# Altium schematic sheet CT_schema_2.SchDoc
size 287 x 169 mm
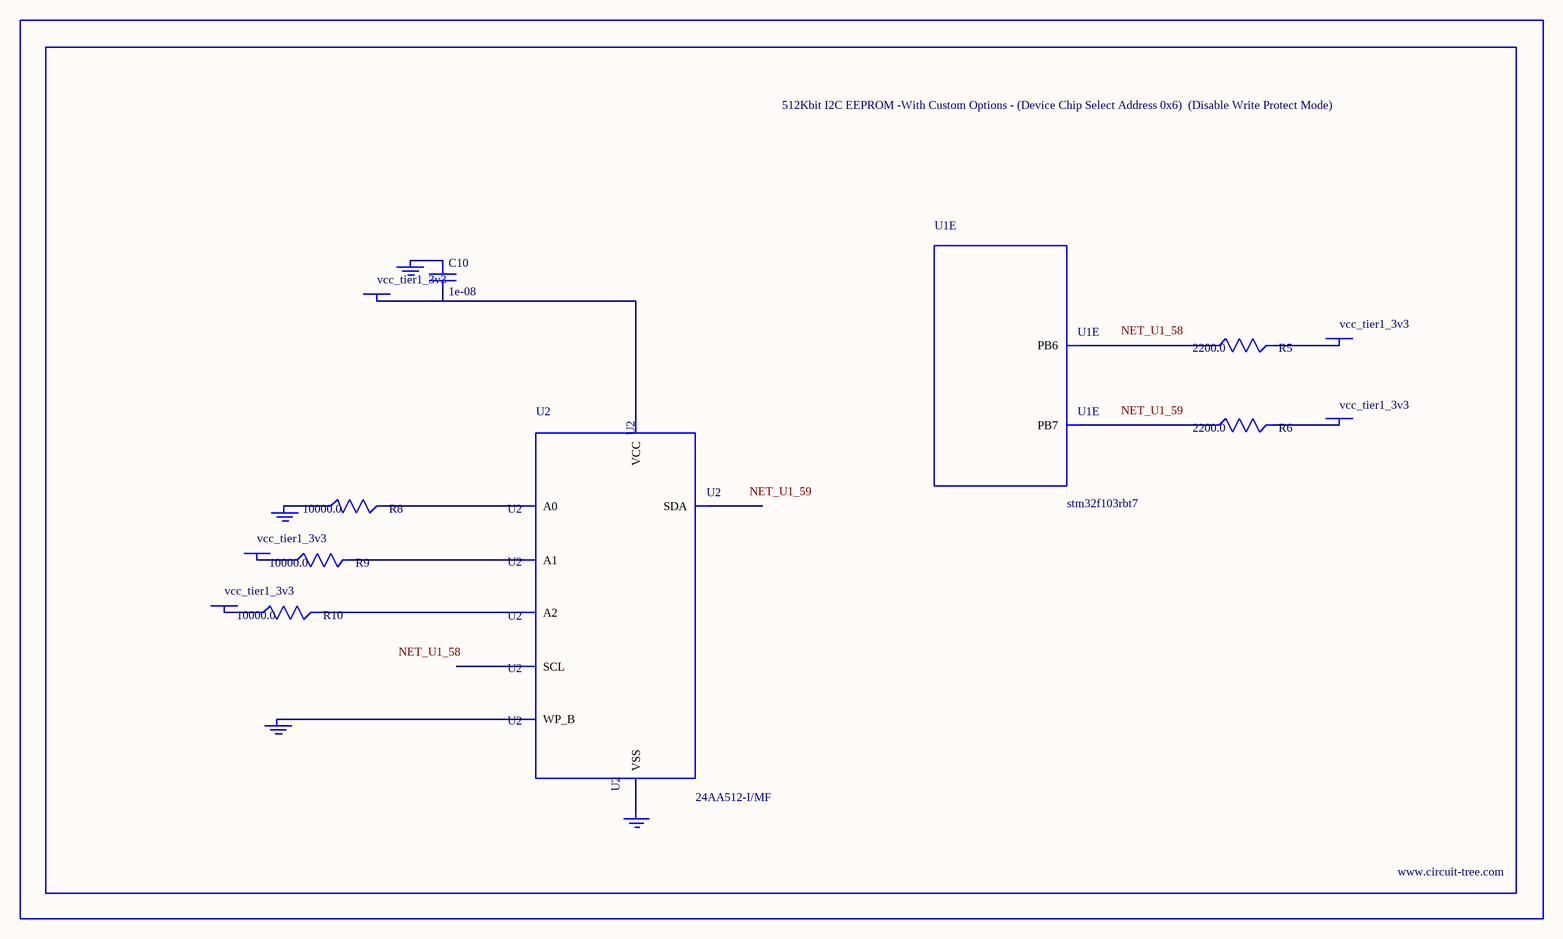
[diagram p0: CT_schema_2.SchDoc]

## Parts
BORDER1  (no value)
C10  1e-08  [C0402]
GND_INSTANCE_1_0  (no value)
GND_INSTANCE_1_1  (no value)
GND_INSTANCE_1_2  (no value)
GND_INSTANCE_1_3  (no value)
POWER_INSTANCE_1_0  vcc_tier1_3v3
POWER_INSTANCE_1_1  vcc_tier1_3v3
POWER_INSTANCE_1_2  vcc_tier1_3v3
POWER_INSTANCE_1_3  vcc_tier1_3v3
POWER_INSTANCE_1_4  vcc_tier1_3v3
R5  2200.0  [R0603]
R6  2200.0  [R0603]
R8  10000.0  [R0603]
R9  10000.0  [R0603]
R10  10000.0  [R0603]
U1  stm32f103rbt7  [LQFP64]  (part E of 7)
U2  24AA512-I/MF  [DFN8-S]

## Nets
NetC10_1: C10.1 GND_INSTANCE_1_2.0(GND)
NetC10_2: C10.2 POWER_INSTANCE_1_2.0(PWR) U2.8(VCC)
NetGND_INSTANCE_1_0_0: GND_INSTANCE_1_0.0(GND) R8.1
NetGND_INSTANCE_1_1_0: GND_INSTANCE_1_1.0(GND) U2.7(WP_B)
NetGND_INSTANCE_1_3_0: GND_INSTANCE_1_3.0(GND) U2.4(VSS)
NetPOWER_INSTANCE_1_0_0: POWER_INSTANCE_1_0.0(PWR) R9.1
NetPOWER_INSTANCE_1_1_0: POWER_INSTANCE_1_1.0(PWR) R10.1
NetPOWER_INSTANCE_1_3_0: POWER_INSTANCE_1_3.0(PWR) R5.2
NetPOWER_INSTANCE_1_4_0: POWER_INSTANCE_1_4.0(PWR) R6.2
NetR5_1: R5.1 U1.58(PB6)
NetR6_1: R6.1 U1.59(PB7)
NetR8_2: R8.2 U2.1(A0)
NetR9_2: R9.2 U2.2(A1)
NetR10_2: R10.2 U2.3(A2)

Not connected (* = marked no-connect by the designer): U2 5(SDA) 6(SCL)

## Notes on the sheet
- Labels drawn without touching a wire or pin: NET_U1_58, NET_U1_59

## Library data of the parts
BORDER1 = BORDER_PAGE1
C10 = C0402C103K3RAC
GND_INSTANCE_1_0-GND_INSTANCE_1_3 = GND
POWER_INSTANCE_1_0-POWER_INSTANCE_1_4 = PWR
R5 R6 = RC0603JR-072K2L
R8-R10 = RC0603JR-0710KL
